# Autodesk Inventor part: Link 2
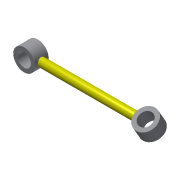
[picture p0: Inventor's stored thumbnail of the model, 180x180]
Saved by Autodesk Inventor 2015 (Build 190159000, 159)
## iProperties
Created: 2020-09
Part Number: Link 2
Material: 一般
Document SubType Name: Modeling
Designer: 徐冠倫
Mass: 0.557027 g
Surface Area: 8.51759 cm^2
Volume: 0.557027 cm^3
Density: 1 g/cm^3
Appearance: 預設
Author: 徐冠倫
Author: IANNIAN
Title: D:\Desktop\OCW-Computer-Aided Engineering Drawing\OCW_Topic 06：組合圖與機構模擬(進階)\6-2_Inventor Studio\Banet\Banet(STP)\Part2.stp
Creation Date: 2020-09-04
Sending System: Autodesk Inventor 2020
Preprocessor: ST-DEVELOPER v18
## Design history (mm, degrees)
node "Part21"
body "Solid1"
node "Base1"
